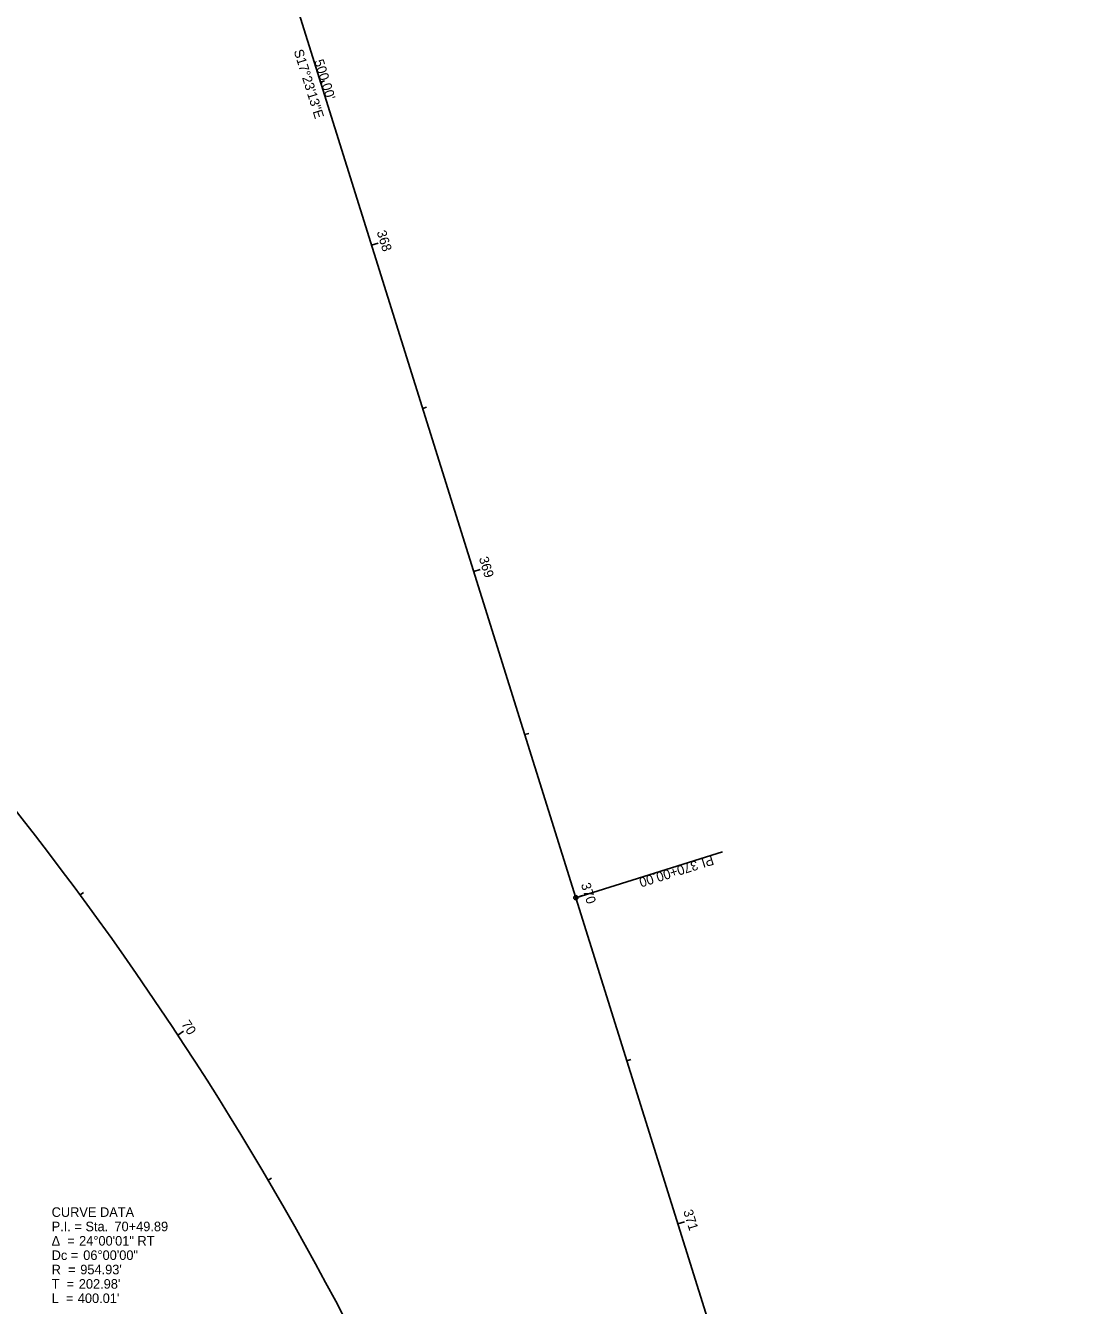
# Model space of a CAD drawing. Extents: x 1918148 to 1920349, y 624677 to 627727.
# Drawn here: x 1919304 to 1919614.4, y 625060.2 to 625434.6 of the extents above; entities that cross this region are included whole.
import ezdxf

# ---------------------------------------------------------------- set-up
doc = ezdxf.new("R2010")
doc.units = 0
for name, color, linetype in [('_CIVIL_CONSTRUCTION', 7, 'Continuous'), ('RS_Raster1', 7, 'Continuous'), ('RW_X_CL', 7, 'Continuous'), ('RW_X_CL_100_Bearings', 7, 'Continuous'), ('RW_X_CL_100_Cardinal_Points', 7, 'Continuous'), ('RW_X_CL_100_Curve_Data', 7, 'Continuous')]:
    doc.layers.add(name, color=color, linetype=linetype)

msp = doc.modelspace()

# ---------------------------------------------------------------- linework, layer by layer
at = {"layer": 'RS_Raster1'}
for p, q in [((1919315.59, 625656.61), (1919465, 625179.46)), ((1919465, 625179.46), (1919614.42, 624702.31))]:
    msp.add_line(p, q, dxfattribs=at)
msp.add_arc((1918551.3, 624613.58), 954.93, 18.58639, 42.58667, dxfattribs=at)
at = {"layer": 'RW_X_CL'}
msp.add_line((1919465, 625179.46), (1919507.95, 625192.91), dxfattribs=at)
msp.add_circle((1919465, 625179.46), 0.6, dxfattribs=at)
at = {"layer": 'RW_X_CL_100_Cardinal_Points'}
for p, q in [((1919390.3, 625418.04), (1919391.44, 625418.4)), ((1919405.24, 625370.32), (1919407.15, 625370.92)), ((1919420.18, 625322.61), (1919421.32, 625322.96)), ((1919435.12, 625274.89), (1919437.03, 625275.49)), ((1919450.06, 625227.18), (1919451.21, 625227.53)), ((1919319.91, 625180.27), (1919320.88, 625180.99)), ((1919465, 625179.46), (1919466.91, 625180.06)), ((1919348.52, 625139.27), (1919350.19, 625140.37)), ((1919479.94, 625131.74), (1919481.09, 625132.1)), ((1919374.94, 625096.83), (1919375.97, 625097.44)), ((1919494.89, 625084.03), (1919496.79, 625084.63))]:
    msp.add_line(p, q, dxfattribs=at)

# ---------------------------------------------------------------- texts
at = {"layer": '_CIVIL_CONSTRUCTION'}
msp.add_text('S17°23\'13"E', height=2.8, rotation=287.387, dxfattribs=at).set_placement((1919382.41, 625427.17))
at = {"layer": 'RW_X_CL'}
for s, p in [('PI', (1919504.82, 625191.88)), ('370+00.00', (1919500.25, 625190.45))]:
    msp.add_text(s, height=2.8, rotation=197.387, dxfattribs=at).set_placement(p)
at = {"layer": 'RW_X_CL_100_Bearings'}
for s, p in [('CURVE DATA', (1919311.59, 625086.08)), ('P.I. = Sta. ', (1919311.59, 625081.88)), ('70+49.89', (1919329.96, 625081.88)), ('Δ  = ', (1919311.59, 625077.68)), ('24°00\'01" RT', (1919319.62, 625077.68)), ('Dc = ', (1919311.59, 625073.48)), ('06°00\'00"', (1919320.83, 625073.48)), ('R  = ', (1919311.59, 625069.28)), ("954.93'", (1919319.96, 625069.28)), ('T  = ', (1919311.59, 625065.08)), ("202.98'", (1919319.53, 625065.08)), ('L  = ', (1919311.59, 625060.88)), ("400.01'", (1919319.24, 625060.88))]:
    msp.add_text(s, height=2.8, dxfattribs=at).set_placement(p)
at = {"layer": 'RW_X_CL_100_Cardinal_Points'}
for s, rotation, p in [('368', 287.387, (1919406.69, 625374.21)), ('369', 287.387, (1919436.58, 625278.76)), ('370', 287.387, (1919466.45, 625183.35)), ('70', 303.4013, (1919349.44, 625142.5)), ('371', 287.387, (1919496.39, 625087.76))]:
    msp.add_text(s, height=2.8, rotation=rotation, dxfattribs=at).set_placement(p)
at = {"layer": 'RW_X_CL_100_Curve_Data'}
msp.add_text("500.00'", height=2.8, rotation=287.387, dxfattribs=at).set_placement((1919388.4, 625424.24))

doc.saveas('drawing.dxf')
